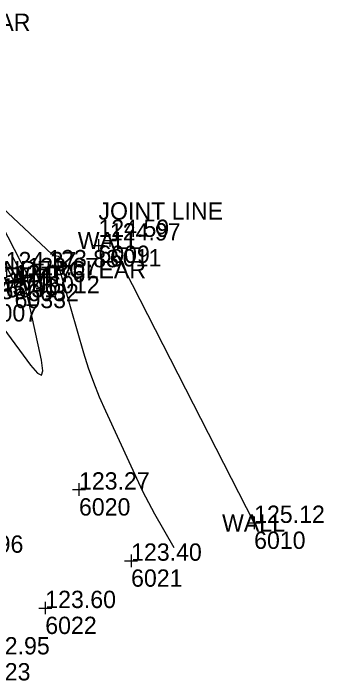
# Model space of a CAD drawing. Extents: x 13482745 to 13483091, y 311698 to 312158.
# Drawn here: x 13482977.4 to 13483034.9, y 311832.8 to 311956.1 of the extents above; entities that cross this region are included whole.
import ezdxf

# ---------------------------------------------------------------- set-up
doc = ezdxf.new("R2010")
doc.units = 0
for name, color, linetype in [('V-BLDG-OTLN', 7, 'Continuous'), ('V-PVMT-ROAD', 7, 'Continuous'), ('V-PVMT-SPOT', 7, 'Continuous'), ('V-SITE-IDEN', 7, 'Continuous'), ('V-SITE-SPOT', 7, 'Continuous'), ('V-SURV-PNTS', 7, 'Continuous'), ('V-SURV-SPOT', 7, 'Continuous'), ('V-TOPO-LINE-IDEN', 7, 'Continuous'), ('V-TOPO-MINR', 7, 'Continuous'), ('V-TOPO-SPOT', 7, 'Continuous')]:
    doc.layers.add(name, color=color, linetype=linetype)

msp = doc.modelspace()

# ---------------------------------------------------------------- linework, layer by layer
at = {"layer": 'V-BLDG-OTLN'}
msp.add_lwpolyline([(13483021.98, 311861.97), (13482995.29, 311914.15)], dxfattribs=at)
at = {"layer": 'V-PVMT-ROAD'}
msp.add_lwpolyline([(13482980.02, 311907.74), (13482977.65, 311906.45), (13482953.44, 311953.97), (13482955.56, 311955.27), (13482980.02, 311907.74)], dxfattribs=at)
at = {"layer": 'V-PVMT-SPOT'}
for p, q in [((13482980.02, 311908.9), (13482980.02, 311906.58)), ((13482977.65, 311907.61), (13482977.65, 311905.29)), ((13482978.82, 311907.74), (13482981.22, 311907.74)), ((13482976.45, 311906.45), (13482978.85, 311906.45))]:
    msp.add_line(p, q, dxfattribs=at)
at = {"layer": 'V-SITE-SPOT'}
for p, q in [((13482993.17, 311914.37), (13482993.17, 311912.05)), ((13482995.29, 311915.31), (13482995.29, 311912.99)), ((13482991.97, 311913.21), (13482994.37, 311913.21)), ((13482994.09, 311914.15), (13482996.49, 311914.15)), ((13483021.98, 311863.13), (13483021.98, 311860.81)), ((13483020.78, 311861.97), (13483023.18, 311861.97))]:
    msp.add_line(p, q, dxfattribs=at)
at = {"layer": 'V-TOPO-MINR'}
for points in [[(13482972.19, 311923.11), (13482984.53, 311911.65), (13482984.65, 311911.55), (13482984.78, 311911.48), (13482984.92, 311911.42), (13482985.07, 311911.38), (13482985.69, 311911.27), (13482985.82, 311911.22), (13482985.9, 311911.15), (13482985.93, 311911.04), (13482985.91, 311910.91), (13482985.71, 311910.27), (13482985.67, 311910.11), (13482985.66, 311909.95), (13482985.67, 311909.79), (13482985.7, 311909.64), (13482990.42, 311893.39), (13482991.27, 311890.65), (13482992.23, 311887.95), (13482993.29, 311885.28), (13482994.45, 311882.66), (13483001.35, 311867.86), (13483001.87, 311866.79), (13483002.41, 311865.72), (13483002.97, 311864.67), (13483003.55, 311863.62), (13483007.14, 311857.41)], [(13482971.34, 311903.64), (13482980.61, 311891.13), (13482981.9, 311889.62), (13482982.66, 311889.26), (13482982.9, 311890.07), (13482982.61, 311892.04), (13482980.23, 311903.05), (13482979.7, 311905.17), (13482979.03, 311907.25), (13482978.23, 311909.28), (13482977.29, 311911.26)]]:
    msp.add_lwpolyline(points, dxfattribs=at)
at = {"layer": 'V-TOPO-SPOT'}
for p, q in [((13482983.88, 311910.36), (13482983.88, 311908.04)), ((13482982.68, 311909.2), (13482985.08, 311909.2)), ((13482989.57, 311869.29), (13482989.57, 311866.97)), ((13482988.37, 311868.13), (13482990.77, 311868.13)), ((13482999.21, 311856.14), (13482999.21, 311853.82)), ((13482998.01, 311854.98), (13483000.41, 311854.98)), ((13482983.33, 311847.4), (13482983.33, 311845.08)), ((13482982.13, 311846.24), (13482984.53, 311846.24))]:
    msp.add_line(p, q, dxfattribs=at)

# ---------------------------------------------------------------- texts
at = {"layer": 'V-PVMT-SPOT'}
for s, p in [('123.67', (13482980.02, 311907.74)), ('124.76', (13482977.65, 311906.45))]:
    msp.add_text(s, height=3.2, dxfattribs=at).set_placement(p)
at = {"layer": 'V-SITE-IDEN'}
for s, p in [('UNDERCLEAR', (13482951.1, 311952.87)), ('JOINT LINE', (13482993.17, 311918.01)), ('UNDERCLEAR', (13482972.49, 311907.18))]:
    msp.add_text(s, height=3.2, dxfattribs=at).set_placement(p)
at = {"layer": 'V-SITE-SPOT'}
for s, p in [('124.59', (13482993.17, 311914.81)), ('124.97', (13482995.29, 311914.15)), ('143.46', (13482972.49, 311903.98)), ('125.12', (13483021.98, 311861.97))]:
    msp.add_text(s, height=3.2, dxfattribs=at).set_placement(p)
at = {"layer": 'V-SURV-PNTS'}
for s, p in [('6009', (13482993.17, 311910.01)), ('6011', (13482995.29, 311909.35)), ('6031', (13482975.99, 311903.64)), ('6012', (13482983.88, 311904.4)), ('6032', (13482980.02, 311902.94)), ('6033', (13482977.65, 311901.65)), ('6007', (13482972.49, 311899.18)), ('6020', (13482989.57, 311863.33)), ('6010', (13483021.98, 311857.17)), ('6021', (13482999.21, 311850.18)), ('6022', (13482983.33, 311841.44)), ('6023', (13482971.07, 311832.87))]:
    msp.add_text(s, height=3.2, dxfattribs=at).set_placement(p)
at = {"layer": 'V-SURV-SPOT'}
msp.add_text('124.37', height=3.2, dxfattribs=at).set_placement((13482975.99, 311908.84))
at = {"layer": 'V-TOPO-LINE-IDEN'}
for s, p in [('WALL', (13482989.34, 311912.55)), ('E/PVMT', (13482970.84, 311906.14)), ('E/PVMT', (13482968.46, 311904.85)), ('WALL', (13483016.04, 311860.37))]:
    msp.add_text(s, height=3.2, dxfattribs=at).set_placement(p)
at = {"layer": 'V-TOPO-SPOT'}
for s, p in [('123.83', (13482983.88, 311909.2)), ('123.56', (13482966.73, 311903.3)), ('123.27', (13482989.57, 311868.13)), ('122.96', (13482966.19, 311856.46)), ('123.40', (13482999.21, 311854.98)), ('123.60', (13482983.33, 311846.24)), ('122.95', (13482971.07, 311837.67))]:
    msp.add_text(s, height=3.2, dxfattribs=at).set_placement(p)

doc.saveas('drawing.dxf')
